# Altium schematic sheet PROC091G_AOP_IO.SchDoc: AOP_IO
size 431 x 279 mm; Date: Not shown in title block; ApprovedBy: Not shown in title block; CheckedBy: Not shown in title block; Author: Not shown in title block; CompanyName: Not shown in title block; DrawnBy: Antony/Bala; Engineer: Not shown in title block; Organization: Not shown in title block; Address1: Not shown in title block; Address2: Not shown in title block; Address3: Not shown in title block; Address4: Not shown in title block; DocumentNumber: 3; Revision: Use project parameter SCH_Rev; SheetNumber: 3; SheetTotal: 12; PageSetup: Record=PageOptions¦CenterHorizontal=True¦CenterVertical=True¦PrintScale=1.00¦XCorrection=1.00¦YCorrection=1.00¦PrintKind=0¦BorderSize=5000000¦LeftOffset=0¦BottomOffset=0¦Orientation=2¦PaperLength=1000¦PaperWidth=1000¦Scale=100¦PaperSource=15¦PrintQuality=600¦MediaType=1¦DitherType=10¦PaperKind=Letter¦PrintScaleMode=1
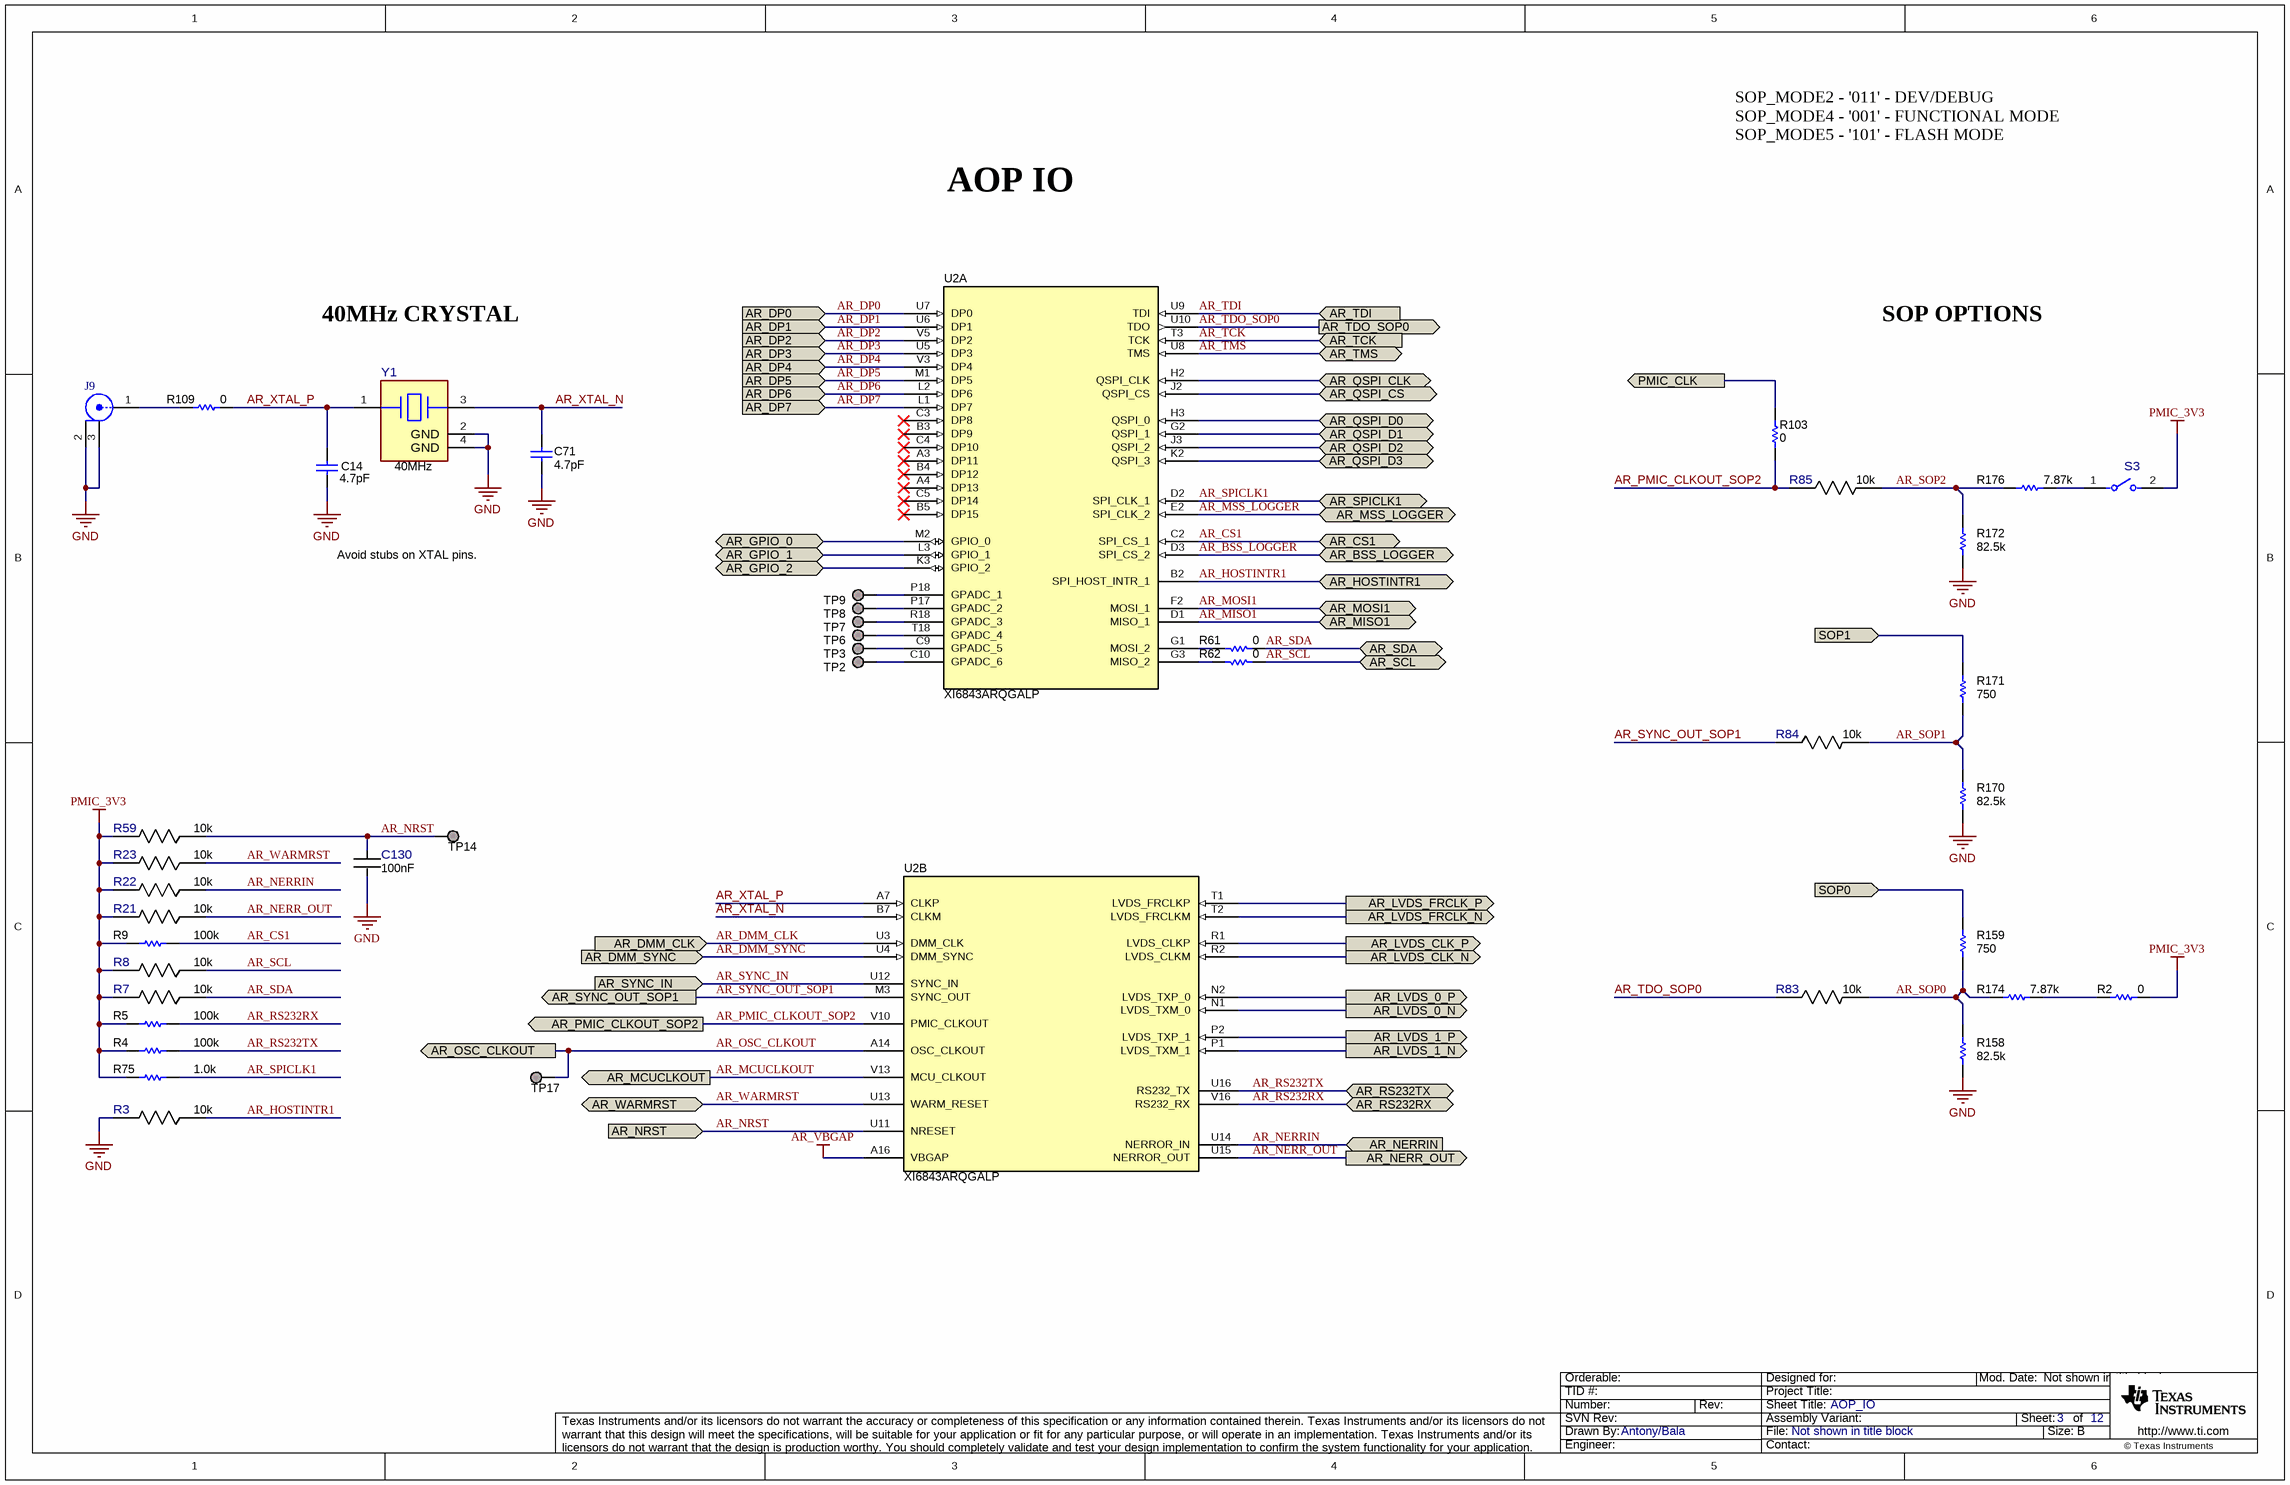
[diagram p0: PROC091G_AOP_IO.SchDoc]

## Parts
C14  value 4.7pF  [0201_033L]  (hidden comment: GRM0335C1H4R7BA01D)
C71  value 4.7pF  [0201_033L]  (hidden comment: GRM0335C1H4R7BA01D)
C130  Cap_F: 100nF  [FP-GRM033R6YA104KE14D_0201 (0603 Metric)-IPC_C]  (hidden comment: GRM033R6YA104KE14D)
J9  U.FL-R-SMT-1(01)  [CONN_UFL-R-SMT-1]  (value not drawn)
R2  Res_ohm: 0  [FP-RC0201JR-070RL_0201 (0603 Metric)-MFG]  (hidden comment: RC0201JR-070RL)
R3  Res_ohm: 10k  [FP-RR0306P-103-D_0201-IPC_C]  (hidden comment: RR0306P-103-D)
R4  value 100k  [0201L]  (hidden comment: CRCW0201100KFKED)
R5  value 100k  [0201L]  (hidden comment: CRCW0201100KFKED)
R7  Res_ohm: 10k  [FP-RR0306P-103-D_0201-IPC_C]  (hidden comment: RR0306P-103-D)
R8  Res_ohm: 10k  [FP-RR0306P-103-D_0201-IPC_C]  (hidden comment: RR0306P-103-D)
R9  value 100k  [0201L]  (hidden comment: CRCW0201100KFKED)
R21  Res_ohm: 10k  [FP-RR0306P-103-D_0201-IPC_C]  (hidden comment: RR0306P-103-D)
R22  Res_ohm: 10k  [FP-RR0306P-103-D_0201-IPC_C]  (hidden comment: RR0306P-103-D)
R23  Res_ohm: 10k  [FP-RR0306P-103-D_0201-IPC_C]  (hidden comment: RR0306P-103-D)
R59  Res_ohm: 10k  [FP-RR0306P-103-D_0201-IPC_C]  (hidden comment: RR0306P-103-D)
R61  Res_ohm: 0  [FP-RC0201JR-070RL_0201 (0603 Metric)-MFG]  (hidden comment: RC0201JR-070RL)
R62  Res_ohm: 0  [FP-RC0201JR-070RL_0201 (0603 Metric)-MFG]  (hidden comment: RC0201JR-070RL)
R75  value 1.0k  [0201L]  (hidden comment: RC0201JR-071KL)
R83  Res_ohm: 10k  [FP-RR0306P-103-D_0201-IPC_C]  (hidden comment: RR0306P-103-D)
R84  Res_ohm: 10k  [FP-RR0306P-103-D_0201-IPC_C]  (hidden comment: RR0306P-103-D)
R85  Res_ohm: 10k  [FP-RR0306P-103-D_0201-IPC_C]  (hidden comment: RR0306P-103-D)
R103  Res_ohm: 0  [FP-RC0201JR-070RL_0201 (0603 Metric)-IPC_C]  (hidden comment: RC0201JR-070RL)
R109  Res_ohm: 0  [FP-RC0201JR-070RL_0201 (0603 Metric)-MFG]  (hidden comment: RC0201JR-070RL)
R158  value 82.5k  [0201L]  (hidden comment: RC0201FR-0782K5L)
R159  value 750  [0201L]  (hidden comment: RC0201JR-07750RL)
R170  value 82.5k  [0201L]  (hidden comment: RC0201FR-0782K5L)
R171  value 750  [0201L]  (hidden comment: RC0201JR-07750RL)
R172  value 82.5k  [0201L]  (hidden comment: RC0201FR-0782K5L)
R174  value 7.87k  [0201L]  (hidden comment: RC0201FR-077K87L)
R176  value 7.87k  [0201L]  (hidden comment: RC0201FR-077K87L)
S3  CHS-01TA  [FP-CHS-01TA_SMT_SW_5MM4_2MM5-MFG]  (value not drawn)
TP2  TESTPOINT  [TP_25MIL-SMT]  (value not drawn)  (no BOM)
TP3  TESTPOINT  [TP_25MIL-SMT]  (value not drawn)  (no BOM)
TP6  TESTPOINT  [TP_25MIL-SMT]  (value not drawn)  (no BOM)
TP7  TESTPOINT  [TP_25MIL-SMT]  (value not drawn)  (no BOM)
TP8  TESTPOINT  [TP_25MIL-SMT]  (value not drawn)  (no BOM)
TP9  TESTPOINT  [TP_25MIL-SMT]  (value not drawn)  (no BOM)
TP14  TESTPOINT  [TP_25MIL-SMT]  (value not drawn)  (no BOM)
TP17  TESTPOINT  [TP_25MIL-SMT]  (value not drawn)  (no BOM)
U2  XI6843ARQGALP  [ALP0180A]  (parts A,B of 4)
Y1  Frequency_Fixed: 40MHz  [FP-CX2016DB40000D0FLJCC_SMT_2MM0_1MM6-MFG]  (hidden comment: CX2016DB40000D0FLJCC)

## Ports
AR_BSS_LOGGER (bidir), AR_CS1 (bidir), AR_DMM_CLK (in), AR_DMM_SYNC (in), AR_DP0 (in), AR_DP1 (in), AR_DP2 (in), AR_DP3 (in), AR_DP4 (in), AR_DP5 (in), AR_DP6 (in), AR_DP7 (in), AR_GPIO_0 (bidir), AR_GPIO_1 (bidir), AR_GPIO_2 (bidir), AR_HOSTINTR1 (bidir), AR_LVDS_0_N (out), AR_LVDS_0_P (out), AR_LVDS_1_N (out), AR_LVDS_1_P (out), AR_LVDS_CLK_N (out), AR_LVDS_CLK_P (out), AR_LVDS_FRCLK_N (out), AR_LVDS_FRCLK_P (out), AR_MCUCLKOUT (out), AR_MISO1 (bidir), AR_MOSI1 (bidir), AR_MSS_LOGGER (bidir), AR_NERR_OUT (out), AR_NERRIN (in), AR_NRST (in), AR_OSC_CLKOUT (out), AR_PMIC_CLKOUT_SOP2 (out), AR_QSPI_CLK (bidir), AR_QSPI_CS (bidir), AR_QSPI_D0 (bidir), AR_QSPI_D1 (bidir), AR_QSPI_D2 (bidir), AR_QSPI_D3 (bidir), AR_RS232RX (bidir), AR_RS232TX (bidir), AR_SCL (bidir), AR_SDA (bidir), AR_SPICLK1 (bidir), AR_SYNC_IN (in), AR_SYNC_OUT_SOP1 (out), AR_TCK (in), AR_TDI (in), AR_TDO_SOP0 (out), AR_TMS (bidir), AR_WARMRST (bidir), PMIC_CLK (out), SOP0 (in), SOP1 (in)

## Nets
AR_VBGAP: U2.A16(VBGAP)
GND: C14.1 C71.1 C130.2 J9.2 J9.3 R3.2 R158.1 R170.1 R172.1 Y1.2(GND) Y1.4(GND)
PMIC_3V3: R2.1 R4.1 R5.1 R7.2 R8.2 R9.1 R21.2 R22.2 R23.2 R59.2 R75.1 S3.2
AR_BSS_LOGGER: U2.D3(SPI_CS_2) ; port AR_BSS_LOGGER
AR_CS1: R9.2 U2.C2(SPI_CS_1) ; port AR_CS1
AR_DMM_CLK: U2.U3(DMM_CLK) ; port AR_DMM_CLK
AR_DMM_SYNC: U2.U4(DMM_SYNC) ; port AR_DMM_SYNC
AR_DP0: U2.U7(DP0) ; port AR_DP0
AR_DP1: U2.U6(DP1) ; port AR_DP1
AR_DP2: U2.V5(DP2) ; port AR_DP2
AR_DP3: U2.U5(DP3) ; port AR_DP3
AR_DP4: U2.V3(DP4) ; port AR_DP4
AR_DP5: U2.M1(DP5) ; port AR_DP5
AR_DP6: U2.L2(DP6) ; port AR_DP6
AR_DP7: U2.L1(DP7) ; port AR_DP7
AR_GPIO_0: U2.M2(GPIO_0) ; port AR_GPIO_0
AR_GPIO_1: U2.L3(GPIO_1) ; port AR_GPIO_1
AR_GPIO_2: U2.K3(GPIO_2) ; port AR_GPIO_2
AR_HOSTINTR1: R3.1 U2.B2(SPI_HOST_INTR_1) ; port AR_HOSTINTR1
AR_LVDS_0_N: U2.N1(LVDS_TXM_0) ; port AR_LVDS_0_N
AR_LVDS_0_P: U2.N2(LVDS_TXP_0) ; port AR_LVDS_0_P
AR_LVDS_1_N: U2.P1(LVDS_TXM_1) ; port AR_LVDS_1_N
AR_LVDS_1_P: U2.P2(LVDS_TXP_1) ; port AR_LVDS_1_P
AR_LVDS_CLK_N: U2.R2(LVDS_CLKM) ; port AR_LVDS_CLK_N
AR_LVDS_CLK_P: U2.R1(LVDS_CLKP) ; port AR_LVDS_CLK_P
AR_LVDS_FRCLK_N: U2.T2(LVDS_FRCLKM) ; port AR_LVDS_FRCLK_N
AR_LVDS_FRCLK_P: U2.T1(LVDS_FRCLKP) ; port AR_LVDS_FRCLK_P
AR_MCUCLKOUT: U2.V13(MCU_CLKOUT) ; port AR_MCUCLKOUT
AR_MISO1: U2.D1(MISO_1) ; port AR_MISO1
AR_MOSI1: U2.F2(MOSI_1) ; port AR_MOSI1
AR_MSS_LOGGER: U2.E2(SPI_CLK_2) ; port AR_MSS_LOGGER
AR_NERR_OUT: R21.1 U2.U15(NERROR_OUT) ; port AR_NERR_OUT
AR_NERRIN: R22.1 U2.U14(NERROR_IN) ; port AR_NERRIN
AR_NRST: C130.1 R59.1 TP14.1 U2.U11(NRESET) ; port AR_NRST
AR_OSC_CLKOUT: TP17.1 U2.A14(OSC_CLKOUT) ; port AR_OSC_CLKOUT
AR_PMIC_CLKOUT_SOP2: R85.1 R103.1 U2.V10(PMIC_CLKOUT) ; port AR_PMIC_CLKOUT_SOP2
AR_QSPI_CLK: U2.H2(QSPI_CLK) ; port AR_QSPI_CLK
AR_QSPI_CS: U2.J2(QSPI_CS) ; port AR_QSPI_CS
AR_QSPI_D0: U2.H3(QSPI_0) ; port AR_QSPI_D0
AR_QSPI_D1: U2.G2(QSPI_1) ; port AR_QSPI_D1
AR_QSPI_D2: U2.J3(QSPI_2) ; port AR_QSPI_D2
AR_QSPI_D3: U2.K2(QSPI_3) ; port AR_QSPI_D3
AR_RS232RX: R5.2 U2.V16(RS232_RX) ; port AR_RS232RX
AR_RS232TX: R4.2 U2.U16(RS232_TX) ; port AR_RS232TX
AR_SCL: R8.1 R62.2 ; port AR_SCL
AR_SDA: R7.1 R61.2 ; port AR_SDA
AR_SOP0: R83.2 R158.2 R159.1 R174.2
AR_SOP1: R84.2 R170.2 R171.1
AR_SOP2: R85.2 R172.2 R176.2
AR_SPICLK1: R75.2 U2.D2(SPI_CLK_1) ; port AR_SPICLK1
AR_SYNC_IN: U2.U12(SYNC_IN) ; port AR_SYNC_IN
AR_SYNC_OUT_SOP1: R84.1 U2.M3(SYNC_OUT) ; port AR_SYNC_OUT_SOP1
AR_TCK: U2.T3(TCK) ; port AR_TCK
AR_TDI: U2.U9(TDI) ; port AR_TDI
AR_TDO_SOP0: R83.1 U2.U10(TDO) ; port AR_TDO_SOP0
AR_TMS: U2.U8(TMS) ; port AR_TMS
AR_WARMRST: R23.1 U2.U13(WARM_RESET) ; port AR_WARMRST
AR_XTAL_N: C71.2 U2.B7(CLKM) Y1.3
AR_XTAL_P: C14.2 R109.1 U2.A7(CLKP) Y1.1
PMIC_CLK: R103.2 ; port PMIC_CLK
SOP0: R159.2 ; port SOP0
SOP1: R171.2 ; port SOP1
NetJ9_1: J9.1 R109.2
NetR2_2: R2.2 R174.1
NetR61_1: R61.1 U2.G1(MOSI_2)
NetR62_1: R62.1 U2.G3(MISO_2)
NetR176_1: R176.1 S3.1
NetTP2_1: TP2.1 U2.C10(GPADC_6)
NetTP3_1: TP3.1 U2.C9(GPADC_5)
NetTP6_1: TP6.1 U2.T18(GPADC_4)
NetTP7_1: TP7.1 U2.R18(GPADC_3)
NetTP8_1: TP8.1 U2.P17(GPADC_2)
NetTP9_1: TP9.1 U2.P18(GPADC_1)

Not connected (* = marked no-connect by the designer): U2 A3(DP11)* A4(DP13)* B3(DP9)* B4(DP12)* B5(DP15)* C3(DP8)* C4(DP10)* C5(DP14)*

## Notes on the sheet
- SOP_MODE2 - '011' - DEV/DEBUG
  SOP_MODE4 - '001' - FUNCTIONAL MODE
  SOP_MODE5 - '101' - FLASH MODE
- AOP IO
- 40MHz CRYSTAL
- SOP OPTIONS
- Avoid stubs on XTAL pins.

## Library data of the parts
C14 C71 = CMP-0080076-1: CAP, CERM, 4.7 pF, 50 V,+/- 3%, C0G/NP0, 0201; Manufacturer: MuRata; AEC Category: Q200; AEC Qualified: N; Cap_Case: 0201; SizeArea_mm2: 0.18; SizeAreaWB_mm2: 2.08; SizeX_mm: 0.6; SizeY_mm: 0.3; SizeZ_mm: 0.33; TaMax_C: 125°C; TaMin_C: -55°C; U/M: EA; Value2: 50V
C130 = CMP-0086440-1: Cap Ceramic 0.1uF 35V X5R 10% Pad SMD 0201 85C T/R; Manufacturer: Murata Electronics North America; AEC Qualified: No; SizeZ_mm: 0.33mm; Symbol Name: SYM-GRM033R6YA104KE14D; TempCo: 15%
J9 = CMP-0075320-1: Receptacle, Ultra Miniature Coaxial, Male Pin, 50 ohm, SMT; Manufacturer: Hirose Electric Co. Ltd.; CNHeader: False; Gender: Female; ContactFinish: Gold
R2 R61 R62 R103 R109 = CMP-0086442-2: RES SMD 0 OHM JUMPER 1/20W 0201; Manufacturer: Yageo; AEC Qualified: No; Power_W: 50mW; SizeZ_mm: 0.26mm; TempCo: 200ppm/°C; Tolerance_%: 5%; VDC_V: 25V
R3 R7 R8 R21-R23 R59 R83-R85 = CMP-0088002-1: 10 kOhms ±0.5% 0.05W, 1/20W Chip Resistor 0201 (0603 Metric)  Thin Film; Manufacturer: Susumu; AEC Qualified: No; Power_W: 50mW; SizeZ_mm: 0.26mm; Symbol Name: SYM-RR0306P-103-D; TempCo: 25ppm/°C; VDC_V: 15V
R4 R5 R9 = CMP-0027261-3: RES, 100 k, 1%, 0.05 W, 0201; Manufacturer: Vishay-Dale; AEC Category: Q200; AEC Qualified: N; EIA_Code: E96; Power_W: 50mW; SizeArea_mm2: 0.18; SizeX_mm: 0.6; SizeY_mm: 0.3; SizeZ_mm: 0.26; TempCo: 100 ppm/C; Value2: 0.05W; VDC_V: 30V
R75 = CMP-0027052-1: RES, 1.0 k, 5%, 0.05 W, 0201; Manufacturer: Yageo America; AEC Category: Q200; AEC Qualified: N; EIA_Code: E24; Power_W: 50mW; Res_ohm: 1k; SizeArea_mm2: 0.18; SizeX_mm: 0.6; SizeY_mm: 0.3; SizeZ_mm: 0.26; TempCo: 200 ppm/C; U/M: EA; Value2: 0.05W; Value_Code: 1k00; VDC_V: 25V
R158 R170 R172 = CMP-0027891-1: RES, 82.5 k, 1%, 0.05 W, 0201; Manufacturer: Yageo America; AEC Category: Q200; AEC Qualified: N; EIA_Code: E96; Power_W: 50mW; SizeArea_mm2: 0.18; SizeX_mm: 0.6; SizeY_mm: 0.3; SizeZ_mm: 0.26; TempCo: 200 ppm/C; U/M: EA; Value2: 0.05W; Value_Code: 82k5; VDC_V: 25V
R159 R171 = CMP-0027165-1: RES, 750, 5%, 0.05 W, 0201; Manufacturer: Yageo America; AEC Category: Q200; AEC Qualified: N; EIA_Code: E24; Power_W: 50mW; SizeArea_mm2: 0.18; SizeX_mm: 0.6; SizeY_mm: 0.3; SizeZ_mm: 0.26; TempCo: 200 ppm/C; U/M: EA; Value2: 0.05W; Value_Code: 750R; VDC_V: 25V
R174 R176 = CMP-0027880-1: RES, 7.87 k, 1%, 0.05 W, 0201; Manufacturer: Yageo America; AEC Category: Q200; AEC Qualified: N; EIA_Code: E96; Power_W: 50mW; SizeArea_mm2: 0.18; SizeX_mm: 0.6; SizeY_mm: 0.3; SizeZ_mm: 0.26; TempCo: 200 ppm/C; U/M: EA; Value2: 0.05W; Value_Code: 7k87; VDC_V: 25V
S3 = CMP-0087181-1: SWITCH SLIDE DIP SPST 100MA 6V; Manufacturer: Nidec Copal Electronics; PositionCount: 1; SizeZ_mm: 2.5mm; Symbol Name: SYM-CHS-01TA
TP2 TP3 TP6-TP9 TP14 TP17 = CMP-0078143-3: TEST POINT.  No entry in BOM.
U2 = CMP-0860942-2: XI6843ARQGALP, ALP0180A (BGA-180); Manufacturer: Texas Instruments; SizeZ_mm: 0.965; SizeX_mm: 15; AEC Qualified: N; SizeArea_mm2: 225; SizeAreaWB_mm2: 289; CompType: IC; AEC Category: Q200
Y1 = CMP-0087164-1: CRYSTAL 40.0000MHZ 8PF SMD; Manufacturer: Kyocera International Inc. Electronic Components; AEC Qualified: No; Frequency Stability: 15ppm; SizeZ_mm: 0.45mm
